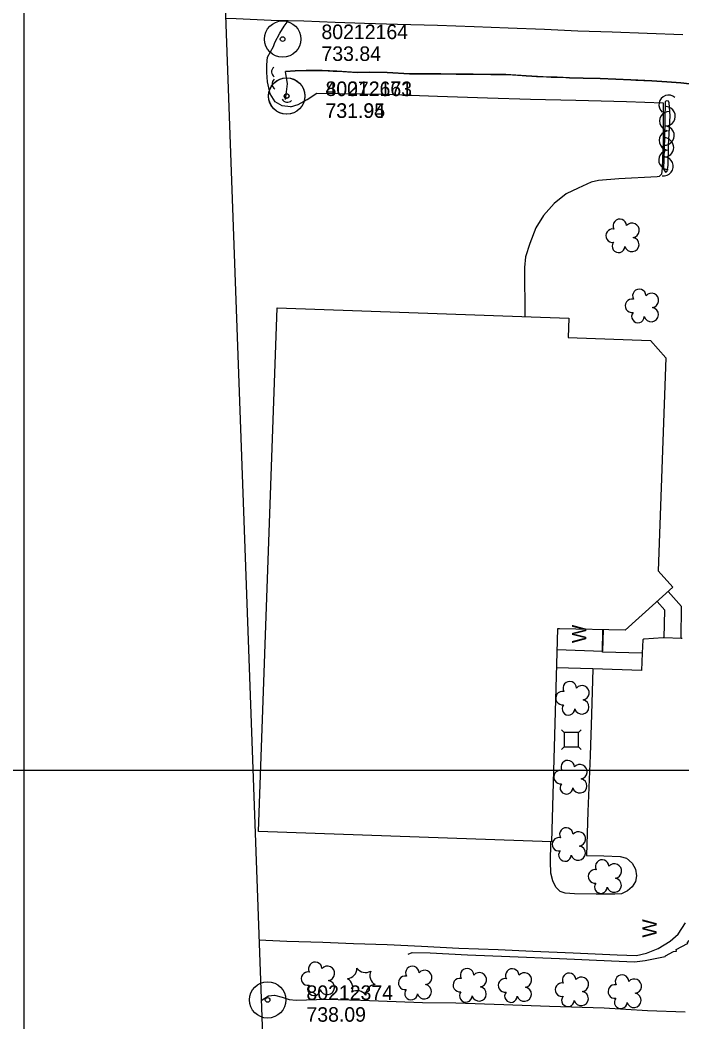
# Model space of a CAD drawing. Extents: x 591954 to 597000, y 198576 to 213500.
# Drawn here: x 593498.2 to 593771.2, y 200896.1 to 201309.4 of the extents above; entities that cross this region are included whole.
import ezdxf

# ---------------------------------------------------------------- set-up
doc = ezdxf.new("R2010")
doc.units = 0
for name, color, linetype in [('Level 10', 7, 'Continuous'), ('Level 11', 7, 'Continuous'), ('Level 12', 7, 'Continuous'), ('Level 15', 7, 'Continuous'), ('Level 17', 7, 'Continuous'), ('Level 18', 7, 'Continuous'), ('Level 19', 7, 'Continuous'), ('Level 21', 7, 'Continuous'), ('Level 4', 7, 'Continuous'), ('Level 6', 7, 'Continuous')]:
    doc.layers.add(name, color=color, linetype=linetype)

msp = doc.modelspace()

# ---------------------------------------------------------------- linework, layer by layer
at = {"layer": 'Level 10'}
for p, q in [((593500, 201000), (593500, 202500)), ((593500, 201000), (593500, 202500)), ((593500, 200000), (593500, 201500)), ((593000, 201000), (595000, 201000)), ((593500, 201000), (595000, 201000)), ((593500, 201000), (595000, 201000)), ((593500, 199500), (593500, 201000))]:
    msp.add_line(p, q, dxfattribs=at)
at = {"layer": 'Level 11'}
for points in [[(593608.76, 201309.08), (593601.79, 201309.26), (593587.3, 201309.89), (593582.99, 201310.11)], [(593771.52, 201303.27), (593756.79, 201303.94), (593742.36, 201304.42), (593728.2, 201304.85), (593714.56, 201305.58), (593699.45, 201306.06), (593685.44, 201306.62), (593670.31, 201307.13), (593653.91, 201307.59), (593640.24, 201308.02), (593628.22, 201308.48), (593615.29, 201308.91), (593608.76, 201309.08)]]:
    msp.add_lwpolyline(points, dxfattribs=at)
at = {"layer": 'Level 12'}
msp.add_lwpolyline([(593596.6, 200974.72), (593604.32, 201190.69), (593724.54, 201186.39), (593724.26, 201178.41), (593758.19, 201177.2), (593764.47, 201170.11), (593761.44, 201082.17), (593767.46, 201075.43), (593747.7, 201057.78), (593720.7, 201058.31), (593719.81, 201058.28), (593717.38, 200970.38), (593596.6, 200974.72)], dxfattribs=at)
at = {"layer": 'Level 15'}
for points in [[(593719.57, 201049.69), (593738.61, 201049.08), (593738.86, 201057.95)], [(593658.35, 200924.05), (593659.92, 200924.69), (593667.41, 200924.55), (593682.81, 200923.76), (593700.21, 200923.14), (593720.7, 200922.28), (593742.14, 200921.31), (593751.55, 200920.87), (593756.05, 200921.49), (593764.2, 200923.13), (593764.33, 200923.42), (593767.76, 200925.2), (593768.88, 200925.24), (593768.88, 200925.24), (593768.83, 200925.94), (593773.44, 200928.49), (593773.6, 200928.42), (593773.43, 200928.9), (593774.21, 200929.75)]]:
    msp.add_lwpolyline(points, dxfattribs=at)
for centre, start, end in [((593604.45, 201288.05), 129.8794, 236.119), ((593604.64, 201283.11), 131.4794, 237.719), ((593608.46, 201278.01), 208.3794, 314.619)]:
    msp.add_arc(centre, 2.5, start, end, dxfattribs=at)
at = {"layer": 'Level 17'}
for points in [[(593609.81, 201273.64), (593606.37, 201273.99), (593603.47, 201275.63), (593601.39, 201278.93), (593600.26, 201283.93), (593600.06, 201287.83), (593599.98, 201291.02), (593600.29, 201294.18), (593602.78, 201298.55), (593603.31, 201300.17), (593605.43, 201304.08), (593607.18, 201306.92)], [(593607.18, 201306.92), (593608.76, 201309.08)], [(593609.81, 201273.64), (593612.97, 201274.56), (593616.62, 201276.68), (593620.65, 201279.25), (593648.2, 201278.79), (593670.42, 201278.02), (593690.93, 201277.37), (593708.73, 201276.82), (593727.38, 201276.36), (593748.31, 201275.87), (593763.47, 201275.34), (593763.37, 201259.41), (593762.98, 201248.33), (593762.73, 201245.82), (593761.78, 201244.89), (593760.94, 201244.71), (593745.21, 201243.99), (593736.77, 201243.18), (593733.77, 201242.55), (593728.43, 201240.13), (593723.38, 201237.69), (593718.55, 201233.71), (593714.11, 201228.83), (593710.97, 201223.75), (593708.46, 201217.31), (593706.66, 201211.78), (593706.21, 201207.36), (593706.34, 201187.04)], [(593770.81, 201054.29), (593770.95, 201067.45), (593765.44, 201073.62)], [(593763.85, 201054.51), (593764.1, 201066.01), (593760.94, 201069.61)], [(593754.81, 201048.27), (593738.38, 201048.62), (593738.6, 201057.96)], [(593763.85, 201054.51), (593763.49, 201054.52), (593755.45, 201054.01), (593755.05, 201053.75), (593754.81, 201048.27)], [(593770.81, 201054.29), (593763.85, 201054.51)], [(593771.28, 201054.28), (593770.81, 201054.29)], [(593754.81, 201048.27), (593754.51, 201041.13), (593734.48, 201041.71)], [(593734.48, 201041.71), (593733.93, 201022.95), (593733.27, 201006.06), (593732.42, 200982.89), (593731.83, 200964.73), (593738.96, 200964.63), (593745.76, 200964.29), (593748.25, 200963.68), (593750.71, 200961.65), (593752.03, 200959.17), (593752.41, 200956.33), (593752.02, 200954.08), (593750.71, 200951.85), (593748.71, 200950.15), (593746.21, 200948.94), (593743.57, 200948.77), (593735.75, 200948.78), (593726.82, 200948.93), (593722.96, 200949.22), (593720.96, 200949.91), (593719.23, 200951.66), (593717.92, 200954.3), (593717.11, 200957.42), (593716.91, 200962.23), (593717.1, 200969.9), (593717.11, 200970.39)], [(593734.48, 201041.71), (593719.36, 201042.25)], [(593734.48, 201041.71), (593734.48, 201041.71)], [(593596.77, 200930), (593608.24, 200929.39), (593623.03, 200929.04), (593635.72, 200928.46), (593649.63, 200928.06), (593663.82, 200927.36), (593679.16, 200926.56), (593695.4, 200925.94), (593709.64, 200925.26), (593726.32, 200924.58), (593744.5, 200923.78), (593752.48, 200923.56), (593756.51, 200924.44), (593761.35, 200926.38), (593766.31, 200929.45), (593769.64, 200932.27), (593772.59, 200937.03)], [(593597.68, 200904.93), (593600.75, 200906.86), (593603.1, 200907.11), (593606.37, 200906.35), (593609.21, 200905.35), (593612.16, 200905.13), (593624.81, 200905.46), (593638.77, 200905.14), (593664.21, 200904.13), (593677.94, 200903.95), (593697.75, 200903.25), (593716.62, 200902.65), (593739.08, 200901.92), (593757, 200900.85), (593772.57, 200900.29)]]:
    msp.add_lwpolyline(points, dxfattribs=at)
at = {"layer": 'Level 18'}
msp.add_lwpolyline([(593765.65, 201257.68), (593766.32, 201269.94), (593765.91, 201275.24), (593765.58, 201276), (593764.65, 201276.14), (593764.23, 201275.66), (593763.98, 201261.04), (593763.61, 201247.9), (593764.4, 201246.66), (593765.15, 201247.07), (593765.48, 201249.46), (593765.65, 201257.68)], dxfattribs=at)
for centre, radius, start, end in [((593745.57, 201224.55), 2.78, 1.3946, 209.1675), ((593742.57, 201220.48), 2.78, 78.0716, 279.0826), ((593750.61, 201222.69), 2.97, 278.4237, 139.6575), ((593750.5, 201216.84), 2.97, 196.0745, 79.0477), ((593745.03, 201216.08), 2.61, 140.7797, 358.7123), ((593753.58, 201195.62), 2.78, 1.3946, 209.1675), ((593750.58, 201191.54), 2.78, 78.0716, 279.0826), ((593758.62, 201193.76), 2.97, 278.4237, 139.6575), ((593758.51, 201187.91), 2.97, 196.0745, 79.0477), ((593753.04, 201187.14), 2.61, 140.7797, 358.7123), ((593724.92, 201033.77), 2.78, 1.3946, 209.1675), ((593729.96, 201031.91), 2.97, 278.4237, 139.6575), ((593721.92, 201029.69), 2.78, 78.0716, 279.0826), ((593729.85, 201026.06), 2.97, 196.0745, 79.0477), ((593724.38, 201025.3), 2.61, 140.7797, 358.7123), ((593724.09, 201001.22), 2.78, 1.3946, 209.1675), ((593721.09, 200997.14), 2.78, 78.0716, 279.0826), ((593729.13, 200999.36), 2.97, 278.4237, 139.6575), ((593729.02, 200993.51), 2.97, 196.0745, 79.0477), ((593723.55, 200992.74), 2.61, 140.7797, 358.7123), ((593723.48, 200973.47), 2.78, 1.3946, 209.1675), ((593720.48, 200969.39), 2.78, 78.0716, 279.0826), ((593728.52, 200971.61), 2.97, 278.4237, 139.6575), ((593722.94, 200964.99), 2.61, 140.7797, 358.7123), ((593728.41, 200965.75), 2.97, 196.0745, 79.0477), ((593738.29, 200960.24), 2.78, 1.3946, 209.1675), ((593735.29, 200956.16), 2.78, 78.0716, 279.0826), ((593743.33, 200958.38), 2.97, 278.4237, 139.6575), ((593743.22, 200952.53), 2.97, 196.0745, 79.0477), ((593737.75, 200951.76), 2.61, 140.7797, 358.7123), ((593619.97, 200918.03), 2.78, 1.3946, 209.1675), ((593625.02, 200916.17), 2.97, 278.4237, 139.6575), ((593632.84, 200918.23), 4.3, 275.2113, 0.9762), ((593640.65, 200920.78), 4.3, 215.2113, 300.9762), ((593646.77, 200915.29), 4.3, 155.2113, 240.9762), ((593660.01, 200916.3), 2.78, 1.3946, 209.1675), ((593665.06, 200914.44), 2.97, 278.4237, 139.6575), ((593682.57, 200915.37), 2.78, 1.3946, 209.1675), ((593701.21, 200915.27), 2.78, 1.3946, 209.1675), ((593616.97, 200913.96), 2.78, 78.0716, 279.0826), ((593624.9, 200910.32), 2.97, 196.0745, 79.0477), ((593631.14, 200910.18), 4.3, 335.2113, 60.9762), ((593657.01, 200912.22), 2.78, 78.0716, 279.0826), ((593679.57, 200911.29), 2.78, 78.0716, 279.0826), ((593687.62, 200913.51), 2.97, 278.4237, 139.6575), ((593698.21, 200911.19), 2.78, 78.0716, 279.0826), ((593706.25, 200913.41), 2.97, 278.4237, 139.6575), ((593724.69, 200913.49), 2.78, 1.3946, 209.1675), ((593729.74, 200911.63), 2.97, 278.4237, 139.6575), ((593746.47, 200912.72), 2.78, 1.3946, 209.1675), ((593751.52, 200910.86), 2.97, 278.4237, 139.6575), ((593619.44, 200909.56), 2.61, 140.7797, 358.7123), ((593637.26, 200904.69), 4.3, 35.2113, 120.9762), ((593645.07, 200907.25), 4.3, 95.2113, 180.9762), ((593659.48, 200907.82), 2.61, 140.7797, 358.7123), ((593664.94, 200908.58), 2.97, 196.0745, 79.0477), ((593687.51, 200907.66), 2.97, 196.0745, 79.0477), ((593706.14, 200907.56), 2.97, 196.0745, 79.0477), ((593721.69, 200909.42), 2.78, 78.0716, 279.0826), ((593729.62, 200905.78), 2.97, 196.0745, 79.0477), ((593743.47, 200908.64), 2.78, 78.0716, 279.0826), ((593682.04, 200906.89), 2.61, 140.7797, 358.7123), ((593700.67, 200906.79), 2.61, 140.7797, 358.7123), ((593724.16, 200905.02), 2.61, 140.7797, 358.7123), ((593745.94, 200904.24), 2.61, 140.7797, 358.7123), ((593751.4, 200905.01), 2.97, 196.0745, 79.0477)]:
    msp.add_arc(centre, radius, start, end, dxfattribs=at)
for centre, major_axis, ratio, start_param, end_param in [((593765.68, 201274.5), (2.62, 3.02), 0.997626, 0, 3.141593), ((593764.45, 201269.76), (-2.64, -3), 0.998246, 0.667256, 3.808849), ((593765.96, 201267.73), (3.48, 1.97), 0.996143, 1.040229, 4.181822), ((593764, 201261.78), (-2.64, -3), 0.998246, 0.667256, 3.808849), ((593765.8, 201259.72), (2.57, 3.07), 0.998345, 0.670558, 3.812151), ((593763.77, 201256.87), (-1.13, -3.84), 0.998926, 0.265397, 3.406989), ((593765.58, 201251.73), (2.57, 3.07), 0.998345, 0.670558, 3.812151), ((593763.55, 201249.09), (-2.93, -2.72), 0.997856, 0.685589, 3.827182)]:
    msp.add_ellipse(centre, major_axis=major_axis, ratio=ratio, start_param=start_param, end_param=end_param, dxfattribs=at)
at = {"layer": 'Level 19'}
for p, q in [((593621.33, 201288.66), (593625.32, 201288.52)), ((593627.32, 201288.4), (593631.31, 201288.17)), ((593633.31, 201288.05), (593637.3, 201287.85)), ((593639.3, 201287.88), (593643.3, 201287.9)), ((593701.28, 201286.83), (593705.27, 201286.55)), ((593707.26, 201286.42), (593711.26, 201286.19)), ((593713.25, 201286.08), (593717.25, 201285.93)), ((593719.25, 201285.86), (593723.24, 201285.71))]:
    msp.add_line(p, q, dxfattribs=at)
for points in [[(593776.67, 201282.86), (593770.65, 201283.55), (593765.01, 201283.94), (593758.82, 201284.33), (593750.09, 201284.79), (593743.97, 201285.03), (593737.4, 201285.27), (593730.39, 201285.47), (593724.83, 201285.65), (593719.76, 201285.84), (593713.89, 201286.04), (593706.93, 201286.44), (593698.54, 201287.02), (593692.42, 201286.92), (593685.03, 201287.1), (593678.01, 201287.1), (593671.75, 201287.21), (593666.39, 201287.23), (593658.81, 201287.26), (593649.56, 201287.76), (593642.32, 201287.93), (593637, 201287.84), (593628.86, 201288.31), (593622.79, 201288.66), (593616.27, 201288.67), (593611.7, 201288.43), (593607.66, 201288.17)], [(593607.66, 201288.17), (593611.7, 201288.43), (593616.27, 201288.67), (593621.33, 201288.66)], [(593607.7, 201276.62), (593608.13, 201279.85), (593608.48, 201283.17), (593607.66, 201288.17)], [(593607.7, 201276.62), (593608.13, 201279.85), (593608.48, 201283.17), (593607.66, 201288.17)], [(593625.32, 201288.52), (593627.32, 201288.4)], [(593631.31, 201288.17), (593633.31, 201288.05)], [(593637.3, 201287.85), (593639.3, 201287.88)], [(593643.3, 201287.9), (593649.56, 201287.76), (593658.81, 201287.26), (593666.39, 201287.23), (593671.75, 201287.21), (593672.29, 201287.21)], [(593672.29, 201287.21), (593678.01, 201287.1), (593685.03, 201287.1), (593692.42, 201286.92), (593698.54, 201287.02), (593701.28, 201286.83)], [(593705.27, 201286.55), (593706.93, 201286.44), (593707.26, 201286.42)], [(593711.26, 201286.19), (593713.25, 201286.08)], [(593717.25, 201285.93), (593719.25, 201285.86)], [(593723.24, 201285.71), (593724.83, 201285.65), (593730.39, 201285.47), (593737.4, 201285.27), (593743.97, 201285.03), (593750.09, 201284.79), (593752.23, 201284.68)], [(593752.23, 201284.68), (593758.82, 201284.33), (593765.01, 201283.94), (593770.65, 201283.55), (593776.67, 201282.86), (593781.01, 201281.74)]]:
    msp.add_lwpolyline(points, dxfattribs=at)
at = {"layer": 'Level 21'}
for p, q in [((593722.57, 201015.54), (593721.51, 201016.61)), ((593728.57, 201015.54), (593729.63, 201016.6)), ((593721.51, 201008.48), (593722.57, 201009.55)), ((593729.63, 201008.48), (593728.57, 201009.55))]:
    msp.add_line(p, q, dxfattribs=at)
msp.add_lwpolyline([(593722.57, 201009.55), (593728.57, 201009.55), (593728.57, 201015.54), (593722.57, 201015.54)], close=True, dxfattribs=at)
at = {"layer": 'Level 4'}
msp.add_lwpolyline([(593580.74, 201372.18), (593612.63, 200492.46)], dxfattribs=at)
at = {"layer": 'Level 6'}
for centre, radius in [((593606.53, 201301.57), 7.5), ((593606.53, 201301.57), 7.5), ((593606.53, 201301.57), 0.96), ((593606.53, 201301.57), 0.96), ((593608.17, 201278.05), 7.5), ((593608.17, 201278.05), 7.5), ((593608.22, 201278.1), 7.5), ((593608.22, 201278.1), 7.5), ((593608.17, 201278.05), 0.96), ((593608.17, 201278.05), 0.96), ((593608.22, 201278.1), 0.96), ((593608.22, 201278.1), 0.96), ((593600.34, 200905.19), 7.5), ((593600.34, 200905.19), 7.5), ((593600.34, 200905.19), 0.96), ((593600.34, 200905.19), 0.96)]:
    msp.add_circle(centre, radius, dxfattribs=at)

# ---------------------------------------------------------------- texts
at = {"layer": 'Level 15'}
for p in [(593731.81, 201052.39), (593760.81, 200930.9)]:
    msp.add_text('W', height=6, rotation=90, dxfattribs=at).set_placement(p)
at = {"layer": 'Level 6'}
for s, p in [('80212164', (593622.53, 201301.57)), ('80212164', (593622.53, 201301.57)), ('733.84', (593622.53, 201292.57)), ('733.84', (593622.53, 201292.57)), ('40072663', (593624.17, 201278.05)), ('40072663', (593624.17, 201278.05)), ('80212171', (593624.22, 201278.1)), ('80212171', (593624.22, 201278.1)), ('731.94', (593624.17, 201269.05)), ('731.94', (593624.17, 201269.05)), ('731.95', (593624.22, 201269.1)), ('731.95', (593624.22, 201269.1)), ('80212374', (593616.34, 200905.19)), ('80212374', (593616.34, 200905.19)), ('738.09', (593616.34, 200896.19)), ('738.09', (593616.34, 200896.19))]:
    msp.add_text(s, height=6, dxfattribs=at).set_placement(p)

doc.saveas('drawing.dxf')
